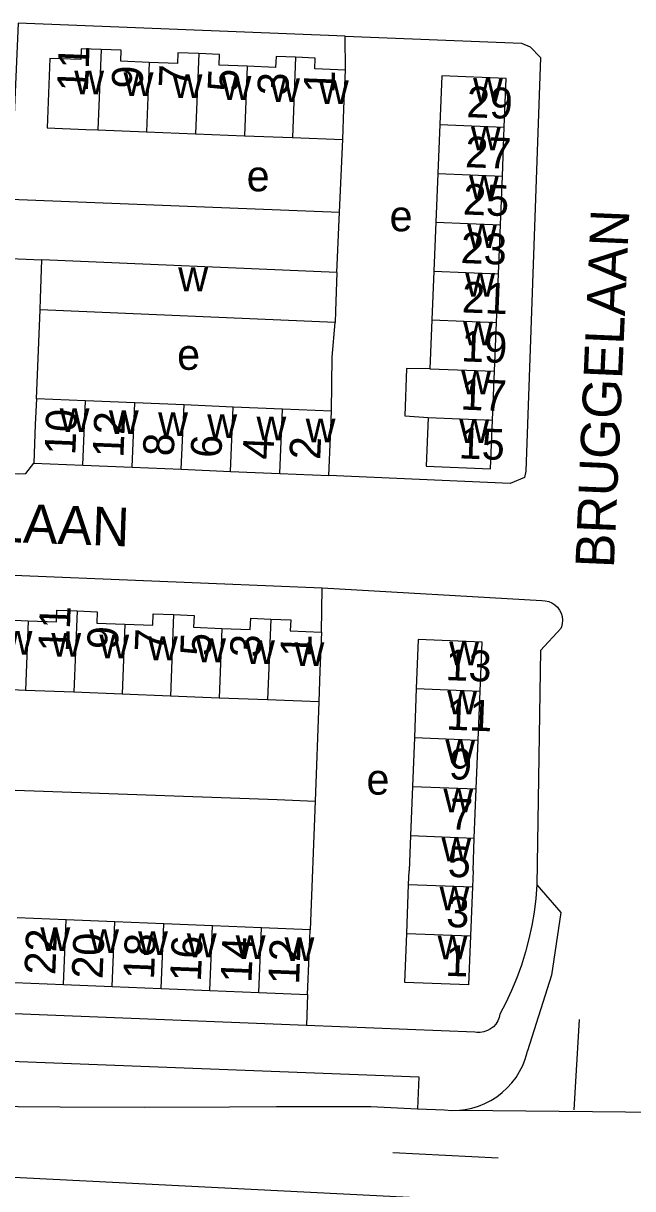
# Model space of a CAD drawing. Extents: x 159675 to 162108, y 386471 to 388472.
# Drawn here: x 161355.1 to 161434, y 387458.8 to 387609.8 of the extents above; entities that cross this region are included whole.
import ezdxf

# ---------------------------------------------------------------- set-up
doc = ezdxf.new("R2010")
doc.units = 0
for name, color, linetype in [('BLT_Basislijn', 7, 'Continuous'), ('BLT_Bebouwing', 7, 'Continuous'), ('BLT_Centroide', 7, 'Continuous'), ('BLT_Huisnummer', 7, 'Continuous'), ('BLT_Huisnummer_ tussenligend', 7, 'Continuous'), ('BLT_Onderverdeling_panden', 7, 'Continuous'), ('BLT_Straatnaam', 7, 'Continuous'), ('BLT_Vlakafsluiter', 7, 'Continuous')]:
    doc.layers.add(name, color=color, linetype=linetype)

msp = doc.modelspace()

# ---------------------------------------------------------------- linework, layer by layer
at = {"layer": 'BLT_Basislijn'}
for p, q in [((161396.74, 387608.14), (161354.38, 387609.8)), ((161396.76, 387603.72), (161396.74, 387608.14)), ((161396, 387585.35), (161396.41, 387594.74)), ((161395.66, 387577.51), (161396, 387585.35)), ((161356.77, 387561.16), (161357.25, 387572.66)), ((161291.22, 387540.84), (161393.74, 387536.65)), ((161393.66, 387530.92), (161393.74, 387536.65)), ((161393.74, 387536.65), (161422.19, 387535.02)), ((161393.31, 387521.88), (161392.83, 387509.01)), ((161392.83, 387509.01), (161392.21, 387492.36)), ((161423.45, 387486.45), (161420.35, 387476.65)), ((161391.74, 387479.96), (161288.2, 387484.03)), ((161391.87, 387483.97), (161391.74, 387479.96)), ((161413.5, 387479.1), (161391.74, 387479.96)), ((161427.04, 387480.71), (161426.32, 387469)), ((161406.09, 387469.17), (161409.6, 387469)), ((161402.9, 387463.5), (161416.52, 387462.78))]:
    msp.add_line(p, q, dxfattribs=at)
for points in [[(161354.38, 387609.8), (161353.42, 387587.03), (161396, 387585.35)], [(161396.74, 387608.14), (161419.58, 387607.24), (161420.68, 387606.75), (161422.03, 387605.36), (161420.12, 387551.76), (161419.96, 387550.94), (161418.08, 387550.17), (161394.62, 387551.2)], [(161267.74, 387584.28), (161266.67, 387555.13), (161266.93, 387554.97), (161354.4, 387551.42), (161355.4, 387551.45), (161356.41, 387552.82)], [(161348.34, 387580.96), (161348.28, 387579.53), (161357.46, 387579.14)], [(161394.98, 387559.54), (161395.03, 387566.56), (161395.43, 387571.02)], [(161422.19, 387535.02), (161422.64, 387534.99), (161423.08, 387534.89), (161423.5, 387534.71), (161423.88, 387534.45), (161424.21, 387534.14), (161424.48, 387533.77), (161424.68, 387533.36), (161424.81, 387532.93), (161424.86, 387532.47), (161424.83, 387532.02), (161424.72, 387531.58), (161424.65, 387531.39)], [(161424.65, 387531.39), (161422.02, 387528.52), (161421.54, 387498.16)], [(161345.49, 387510.72), (161387.92, 387509.21), (161392.83, 387509.01)], [(161421.54, 387498.16), (161421.41, 387496.4), (161421.19, 387494.65), (161420.9, 387492.9), (161420.53, 387491.18), (161420.08, 387489.47), (161419.56, 387487.78), (161418.95, 387486.12), (161418.28, 387484.49), (161417.53, 387482.89), (161416.76, 387481.43)], [(161421.54, 387498.16), (161424.65, 387494.58), (161423.45, 387486.45)], [(161416.76, 387481.43), (161416.66, 387480.97), (161416.48, 387480.54), (161416.23, 387480.14), (161415.92, 387479.79), (161415.55, 387479.5), (161415.14, 387479.28), (161414.69, 387479.13), (161414.23, 387479.06), (161413.76, 387479.06), (161413.5, 387479.1)], [(161275.79, 387478.32), (161406.25, 387473.3), (161406.09, 387469.17)], [(161411.52, 387468.98), (161412.26, 387469.06), (161413.13, 387469.24), (161413.98, 387469.5), (161414.81, 387469.83), (161415.6, 387470.24), (161416.35, 387470.72), (161417.06, 387471.26), (161417.71, 387471.86), (161418.31, 387472.52), (161418.85, 387473.23), (161419.32, 387473.98), (161419.72, 387474.78), (161420.05, 387475.6), (161420.3, 387476.46), (161420.35, 387476.65)], [(161261.45, 387473.3), (161272.37, 387472.55), (161283.29, 387471.87), (161294.22, 387471.28), (161305.15, 387470.77), (161316.09, 387470.33), (161327.02, 387469.98), (161337.96, 387469.71), (161348.91, 387469.51), (161359.85, 387469.4), (161370.79, 387469.37), (161381.74, 387469.41), (161387.85, 387469.47)], [(161387.85, 387469.47), (161400.04, 387469.47), (161406.09, 387469.17)], [(161409.6, 387469), (161410.48, 387468.94), (161411.52, 387468.98)], [(161260.28, 387465.84), (161302.6, 387464.08), (161334.1, 387461.28), (161405.05, 387457.71)]]:
    msp.add_lwpolyline(points, dxfattribs=at)
at = {"layer": 'BLT_Bebouwing'}
for p, q in [((161371, 387595.74), (161377.36, 387595.49)), ((161408.98, 387596.67), (161408.73, 387590.34)), ((161417.08, 387590.01), (161417.33, 387596.33)), ((161377.36, 387595.49), (161383.71, 387595.24)), ((161383.71, 387595.24), (161389.92, 387595)), ((161389.92, 387595), (161396.41, 387594.74)), ((161408.73, 387590.34), (161408.47, 387584.02)), ((161416.82, 387583.68), (161417.08, 387590.01)), ((161408.47, 387584.02), (161408.22, 387577.7)), ((161416.57, 387577.36), (161416.82, 387583.68)), ((161395.66, 387577.51), (161357.46, 387579.14)), ((161408.22, 387577.7), (161407.96, 387571.38)), ((161416.31, 387571.04), (161416.57, 387577.36)), ((161395.43, 387571.02), (161357.25, 387572.66)), ((161407.96, 387571.38), (161407.71, 387565.05)), ((161416.06, 387564.72), (161416.31, 387571.04)), ((161415.8, 387558.4), (161416.06, 387564.72)), ((161363.13, 387560.89), (161356.77, 387561.16)), ((161369.5, 387560.62), (161363.13, 387560.89)), ((161375.87, 387560.35), (161369.5, 387560.62)), ((161382.24, 387560.08), (161375.87, 387560.35)), ((161388.61, 387559.81), (161382.24, 387560.08)), ((161394.98, 387559.54), (161388.61, 387559.81)), ((161356.41, 387552.82), (161362.78, 387552.55)), ((161362.78, 387552.55), (161369.15, 387552.28)), ((161369.15, 387552.28), (161375.52, 387552.01)), ((161375.52, 387552.01), (161381.89, 387551.74)), ((161381.89, 387551.74), (161388.26, 387551.47)), ((161388.26, 387551.47), (161394.62, 387551.2)), ((161355.34, 387523.36), (161349.05, 387523.61)), ((161361.62, 387523.12), (161355.34, 387523.36)), ((161367.85, 387522.87), (161361.62, 387523.12)), ((161405.94, 387523.6), (161405.69, 387517.26)), ((161413.95, 387516.93), (161414.2, 387523.28)), ((161374.11, 387522.63), (161367.85, 387522.87)), ((161380.42, 387522.38), (161374.11, 387522.63)), ((161386.68, 387522.14), (161380.42, 387522.38)), ((161393.31, 387521.88), (161386.68, 387522.14)), ((161405.69, 387517.26), (161405.45, 387510.91)), ((161413.7, 387510.59), (161413.95, 387516.93)), ((161405.45, 387510.91), (161405.2, 387504.57)), ((161413.45, 387504.24), (161413.7, 387510.59)), ((161405.2, 387504.57), (161405.02, 387500)), ((161413.29, 387500), (161413.45, 387504.24)), ((161404.95, 387498.22), (161405.02, 387500)), ((161413.29, 387500), (161413.21, 387497.9)), ((161404.7, 387491.88), (161404.95, 387498.22)), ((161413.21, 387497.9), (161412.96, 387491.56)), ((161360.6, 387493.65), (161354.27, 387493.9)), ((161366.92, 387493.39), (161360.6, 387493.65)), ((161373.25, 387493.13), (161366.92, 387493.39)), ((161379.57, 387492.88), (161373.25, 387493.13)), ((161385.9, 387492.62), (161379.57, 387492.88)), ((161392.21, 387492.36), (161385.9, 387492.62)), ((161353.93, 387485.51), (161360.26, 387485.25)), ((161360.26, 387485.25), (161366.58, 387485)), ((161366.58, 387485), (161372.91, 387484.74)), ((161372.91, 387484.74), (161379.23, 387484.48)), ((161379.23, 387484.48), (161385.56, 387484.23)), ((161385.56, 387484.23), (161391.87, 387483.97))]:
    msp.add_line(p, q, dxfattribs=at)
for points in [[(161365.14, 387606.41), (161362.56, 387606.51), (161362.5, 387605.1), (161358.49, 387605.25), (161358.17, 387596.24), (161363.17, 387596.05), (161364.73, 387595.99)], [(161371.35, 387604.74), (161367.67, 387604.89), (161367.72, 387606.3), (161365.14, 387606.41)], [(161377.77, 387605.87), (161375.08, 387605.97), (161375.03, 387604.6), (161371.35, 387604.74)], [(161384.06, 387604.23), (161380.4, 387604.38), (161380.46, 387605.76), (161377.77, 387605.87)], [(161390.32, 387605.4), (161387.78, 387605.5), (161387.72, 387604.09), (161384.06, 387604.23)], [(161396.76, 387603.72), (161392.82, 387603.88), (161392.87, 387605.3), (161390.32, 387605.4)], [(161396.41, 387594.74), (161396.56, 387598.73), (161396.76, 387603.72)], [(161417.33, 387596.33), (161417.58, 387602.65), (161409.24, 387602.99), (161408.98, 387596.67)], [(161364.73, 387595.99), (161371, 387595.74)], [(161357.25, 387572.66), (161357.3, 387574.15), (161357.46, 387579.14)], [(161395.66, 387577.51), (161395.48, 387572.51), (161395.43, 387571.02)], [(161407.71, 387565.05), (161404.69, 387565.07), (161404.45, 387558.94), (161407.46, 387558.73)], [(161356.77, 387561.16), (161356.62, 387557.82), (161356.41, 387552.82)], [(161394.62, 387551.2), (161394.84, 387556.2), (161394.98, 387559.54)], [(161407.46, 387558.73), (161407.2, 387552.41), (161415.55, 387552.08), (161415.8, 387558.4)], [(161349.46, 387534.11), (161352.09, 387534.01), (161352.03, 387532.55), (161355.7, 387532.4)], [(161355.7, 387532.4), (161359.36, 387532.26), (161359.42, 387533.77), (161362.03, 387533.66)], [(161362.03, 387533.66), (161364.64, 387533.56), (161364.59, 387532.09), (161368.2, 387531.94)], [(161368.2, 387531.94), (161371.82, 387531.8), (161371.88, 387533.29), (161374.52, 387533.19)], [(161374.52, 387533.19), (161377.17, 387533.08), (161377.11, 387531.54), (161380.78, 387531.4)], [(161380.78, 387531.4), (161384.44, 387531.25), (161384.5, 387532.71), (161387.09, 387532.61)], [(161387.09, 387532.61), (161389.69, 387532.51), (161389.63, 387531.07), (161393.66, 387530.92)], [(161393.66, 387530.92), (161393.47, 387525.92), (161393.31, 387521.88)], [(161414.2, 387523.28), (161414.45, 387529.62), (161406.19, 387529.94), (161405.94, 387523.6)], [(161391.87, 387483.97), (161392.07, 387488.97), (161392.21, 387492.36)], [(161412.96, 387491.56), (161412.71, 387485.21), (161404.45, 387485.53), (161404.7, 387491.88)]]:
    msp.add_lwpolyline(points, dxfattribs=at)
at = {"layer": 'BLT_Onderverdeling_panden'}
for p, q in [((161365.14, 387606.41), (161364.73, 387595.99)), ((161371.35, 387604.74), (161371, 387595.74)), ((161377.77, 387605.87), (161377.36, 387595.49)), ((161390.32, 387605.4), (161389.92, 387595)), ((161384.06, 387604.23), (161383.71, 387595.24)), ((161408.98, 387596.67), (161417.33, 387596.33)), ((161408.73, 387590.34), (161417.08, 387590.01)), ((161408.47, 387584.02), (161416.82, 387583.68)), ((161408.22, 387577.7), (161416.57, 387577.36)), ((161407.96, 387571.38), (161416.31, 387571.04)), ((161407.71, 387565.05), (161416.06, 387564.72)), ((161362.78, 387552.55), (161363.13, 387560.89)), ((161369.15, 387552.28), (161369.5, 387560.62)), ((161375.52, 387552.01), (161375.87, 387560.35)), ((161381.89, 387551.74), (161382.24, 387560.08)), ((161388.26, 387551.47), (161388.61, 387559.81)), ((161407.46, 387558.73), (161415.8, 387558.4)), ((161362.03, 387533.66), (161361.62, 387523.12)), ((161355.7, 387532.4), (161355.34, 387523.36)), ((161374.52, 387533.19), (161374.11, 387522.63)), ((161387.09, 387532.61), (161386.68, 387522.14)), ((161368.2, 387531.94), (161367.85, 387522.87)), ((161380.78, 387531.4), (161380.42, 387522.38)), ((161405.94, 387523.6), (161414.2, 387523.28)), ((161405.69, 387517.26), (161413.95, 387516.93)), ((161405.45, 387510.91), (161413.7, 387510.59)), ((161405.2, 387504.57), (161413.45, 387504.24)), ((161404.95, 387498.22), (161413.21, 387497.9)), ((161360.26, 387485.25), (161360.6, 387493.65)), ((161366.58, 387485), (161366.92, 387493.39)), ((161372.91, 387484.74), (161373.25, 387493.13)), ((161379.23, 387484.48), (161379.57, 387492.88)), ((161385.56, 387484.23), (161385.9, 387492.62)), ((161404.7, 387491.88), (161412.96, 387491.56))]:
    msp.add_line(p, q, dxfattribs=at)
at = {"layer": 'BLT_Vlakafsluiter'}
msp.add_line((161411.52, 387468.98), (161442.4, 387468.68), dxfattribs=at)

# ---------------------------------------------------------------- texts
at = {"layer": 'BLT_Centroide'}
for s, p in [('w', (161361.66, 387600.61)), ('w', (161368.05, 387600.36)), ('w', (161374.39, 387600.11)), ('w', (161380.72, 387599.88)), ('w', (161387.02, 387599.62)), ('w', (161393.34, 387599.36)), ('w', (161413.29, 387599.66)), ('w', (161413.02, 387593.34)), ('e', (161383.98, 387588.03)), ('w', (161412.77, 387587)), ('e', (161402.48, 387582.85)), ('w', (161412.52, 387580.69)), ('w', (161375.12, 387575.09)), ('w', (161412.27, 387574.38)), ('w', (161412.01, 387568.06)), ('e', (161374.98, 387564.9)), ('w', (161411.76, 387561.72)), ('w', (161359.77, 387556.86)), ('w', (161366.14, 387556.58)), ('w', (161372.52, 387556.31)), ('w', (161378.88, 387556.05)), ('w', (161385.25, 387555.78)), ('w', (161391.62, 387555.52)), ('w', (161411.51, 387555.41)), ('w', (161352.38, 387528)), ('w', (161358.69, 387527.75)), ('w', (161364.91, 387527.53)), ('w', (161371.19, 387527.28)), ('w', (161377.44, 387527.02)), ('w', (161383.77, 387526.77)), ('w', (161390.17, 387526.53)), ('w', (161410.2, 387526.62)), ('w', (161409.95, 387520.25)), ('w', (161409.7, 387513.91)), ('e', (161399.49, 387509.86)), ('w', (161409.45, 387507.56)), ('w', (161409.2, 387501.22)), ('w', (161408.95, 387494.88)), ('w', (161357.27, 387489.58)), ('w', (161363.59, 387489.33)), ('w', (161369.92, 387489.08)), ('w', (161376.23, 387488.8)), ('w', (161382.56, 387488.55)), ('w', (161388.88, 387488.3)), ('w', (161408.7, 387488.53))]:
    msp.add_text(s, height=4, dxfattribs=at).set_placement(p)
at = {"layer": 'BLT_Huisnummer'}
for s, rotation, p in [('11', 87.7703, (161363.42, 387600.89)), ('5', 87.7703, (161382.91, 387600.87)), ('1', 87.7703, (161395.33, 387600.7)), ('29', 357.6951, (161412.4, 387597.65)), ('23', 357.6951, (161411.64, 387578.75)), ('19', 357.6951, (161411.69, 387566.01)), ('10', 87.5816, (161361.79, 387553.81)), ('15', 357.6951, (161411.38, 387553.44)), ('6', 87.5816, (161380.7, 387553.43)), ('2', 87.5816, (161393.5, 387553.2)), ('9', 87.7534, (161367.31, 387528.63)), ('5', 87.7534, (161379.36, 387527.77)), ('1', 87.7534, (161392.31, 387527.61)), ('13', 357.7598, (161409.67, 387524.71)), ('9', 357.7598, (161410.11, 387511.87)), ('5', 357.7598, (161409.96, 387499.22)), ('20', 87.6847, (161365.32, 387485.93)), ('16', 87.6847, (161378.05, 387485.58)), ('12', 87.6847, (161390.76, 387485.2)), ('1', 357.7598, (161409.65, 387486.4))]:
    msp.add_text(s, height=4, rotation=rotation, dxfattribs=at).set_placement(p)
at = {"layer": 'BLT_Huisnummer_ tussenligend'}
for s, rotation, p in [('9', 87.7648, (161370.49, 387601.26)), ('7', 87.7648, (161376.58, 387601.39)), ('3', 87.7648, (161389.35, 387600.39)), ('27', 357.6951, (161412.21, 387591.17)), ('25', 357.6949, (161411.94, 387585.04)), ('21', 357.7017, (161411.79, 387572.35)), ('17', 357.6946, (161411.62, 387559.76)), ('12', 87.5755, (161368.02, 387553.47)), ('8', 87.5755, (161374.53, 387553.65)), ('4', 87.5755, (161387.44, 387553.21)), ('11', 87.748, (161360.98, 387528.3)), ('7', 87.748, (161373.47, 387528.3)), ('3', 87.748, (161385.8, 387527.59)), ('11', 357.7596, (161409.77, 387518.29)), ('7', 357.7593, (161410.2, 387505.38)), ('3', 357.759, (161409.77, 387492.72)), ('22', 87.6799, (161359.2, 387486.45)), ('18', 87.6799, (161371.98, 387485.87)), ('14', 87.6799, (161384.6, 387485.42))]:
    msp.add_text(s, height=4, rotation=rotation, dxfattribs=at).set_placement(p)
at = {"layer": 'BLT_Straatnaam'}
for s, rotation, p in [('BRUGGELAAN', 87.5147, (161431.52, 387539.16)), ('OOSTENDELAAN', 357.9641, (161313.77, 387543.97))]:
    msp.add_text(s, height=5, rotation=rotation, dxfattribs=at).set_placement(p)

doc.saveas('drawing.dxf')
